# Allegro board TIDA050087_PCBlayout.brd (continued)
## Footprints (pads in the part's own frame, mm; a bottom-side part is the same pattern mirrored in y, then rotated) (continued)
MH_CIR173D106T_CUST
  round 4.394 hole 2.692: 1(0,0)
RC0603
  oval 0.889x1.143 smd: 1(-0.762,0) 2(0.762,0)
RC0805
  oval 0.889x1.524 smd: 1(-0.965,0) 2(0.965,0)
SON8_0P5_3X2_EP_A1
  rect 0.635x0.254 smd: 1(-1.412,0.75) 2(-1.412,0.25) 3(-1.412,-0.25) 4(-1.412,-0.75) 5(1.412,-0.75) 6(1.412,-0.25) 7(1.412,0.25) 8(1.412,0.75)
  rect 1.6x1.6 smd: 9(0,0)
SOT23-3L_1P9_2P9X1P3_A1
  rect 0.813x0.914 smd: 1(-0.95,-1) 2(0.95,-1) 3(0,1)
SOT23-5L_0P95_2P9X1P6_E_A1
  rect 0.61x1.092 smd: 1(-0.95,-1.3) 2(0,-1.3) 3(0.95,-1.3) 4(0.95,1.3) 5(-0.95,1.3)
SOT23-6L_0P95_2P9X1P6_K_A1
  rect 0.61x1.118 smd: 1(-0.95,-1.321) 2(0,-1.321) 3(0.95,-1.321) 4(0.95,1.321) 5(0,1.321) 6(-0.95,1.321)
SOT323-3L_1P3_2X1P25_A2
  rect 0.711x0.889 smd: 1(-0.648,-0.952) 2(0.648,-0.952) 3(0,0.952)
SOT563-6L_0P5_1P6X1P2_A_A1
  rect 0.305x0.66 smd: 1(-0.5,-0.74) 2(0,-0.74) 3(0.5,-0.74) 4(0.5,0.74) 5(0,0.74) 6(-0.5,0.74)
TP20_SMD
  round 0.381 smd: 1(0,0)
TP35_SMD
  round 0.889 smd: 1(0,0)
TP50_SMD
  round 1.27 smd: 1(0,0)
unnamed#2
  round 0.508 smd: (0,0)
UQFN16_0P65_4X4_EP_A1
  rect 0.787x0.356 smd: 1(-1.975,0.975) 2(-1.975,0.325) 3(-1.975,-0.325) 4(-1.975,-0.975) 9(1.975,-0.975) 10(1.975,-0.325) 11(1.975,0.325) 12(1.975,0.975)
  rect 0.356x0.787 smd: 5(-0.975,-1.975) 6(-0.325,-1.975) 7(0.325,-1.975) 8(0.975,-1.975) 13(0.975,1.975) 14(0.325,1.975) 15(-0.325,1.975) 16(-0.975,1.975)
  rect 2.692x2.692 smd: 17(0,0)
VQFN32_0P4_4X4_EP_A1
  rect 0.559x0.203 smd: 1(-1.925,1.4) 2(-1.925,1) 3(-1.925,0.6) 4(-1.925,0.2) 5(-1.925,-0.2) 6(-1.925,-0.6) 7(-1.925,-1) 8(-1.925,-1.4) 17(1.925,-1.4) 18(1.925,-1) 19(1.925,-0.6) 20(1.925,-0.2) 21(1.925,0.2) 22(1.925,0.6) 23(1.925,1) 24(1.925,1.4)
  rect 0.203x0.559 smd: 9(-1.4,-1.925) 10(-1,-1.925) 11(-0.6,-1.925) 12(-0.2,-1.925) 13(0.2,-1.925) 14(0.6,-1.925) 15(1,-1.925) 16(1.4,-1.925) 25(1.4,1.925) 26(1,1.925) 27(0.6,1.925) 28(0.2,1.925) 29(-0.2,1.925) 30(-0.6,1.925) 31(-1,1.925) 32(-1.4,1.925)
  rect 2.794x2.794 smd: 33(0,0)
WSON10_0P5_2X3_EP_B_A1
  rect 0.457x0.254 smd: 1(-0.975,1) 2(-0.975,0.5) 3(-0.975,0) 4(-0.975,-0.5) 5(-0.975,-1) 6(0.975,-1) 7(0.975,-0.5)
  rect 0.559x1.499 smd: 10(0.975,0.58)
  rect 1.092x2.692 smd: 11(0,0)
X2SON4_0P65_1X1_EP_A1
  custom 0.077x0.077 smd: 1(-0.43,0.325) 2(-0.43,-0.325) 3(0.43,-0.325) 4(0.43,0.325)
  rect 0.483x0.483 smd rot 45: 5(0,0)
XTAL2_2P5_3P2X1P5
  rect 1.092x1.905 smd: 1(-1.25,0) 2(1.25,0)
XTAL4_1P6_3P2X2P5_A_A1
  rect 1.397x1.194 smd: 1(-1.1,-0.8) 2(1.1,-0.8) 3(1.1,0.8) 4(-1.1,0.8)

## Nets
GND: BH801.1 BH802.1 BH803.1 BH804.1 C101.2 C102.2 C106.2 C107.2 C108.2 C109.2 C110.2 C111.2 C114.2 C116.2 C117.2 C118.2 C119.2 C124.2 C129.2 C130.2 C131.2 C132.2 C134.2 C135.2 C136.2 C137.2 C138.2 C139.2 C140.2 C141.2 C142.2 C143.2 C144.2 C145.2 C146.2 C147.2 C148.2 C149.2 C151.2 C152.2 C153.2 C154.2 C155.2 C156.2 C201.2 C202.2 C203.2 C204.2 C205.2 C206.2 C207.2 C208.2 C209.2 C210.2 C211.2 C212.2 C213.2 C214.2 C215.2 C216.2 C217.2 C218.2 C219.2 C220.2 C221.2 C222.2 C401.2 C402.2 C403.2 C404.2 C405.2 C501.2 C502.2 C503.2 C504.2 C505.2 C506.2 C507.2 C508.2 C509.2 C702.1 C704.1 C706.1 C707.2 C708.2 C709.2 C712.1 C713.2 C714.2 C715.1 C718.2 C720.2 C721.1 C722.1 C723.1 C724.1 C725.2 C726.2 C727.2 C729.2 C730.2 C731.2 C801.2 C802.2 C803.2 C804.2 C805.2 C806.2 C807.2 C808.2 C809.2 C901.2 C903.2 C904.2 C906.2 C909.2 C911.2 C912.2 C913.2 C914.2 C915.2 C916.2 C918.2 C922.2 C923.2 C925.2 C926.2 C928.2 C929.2 C930.2 C931.2 C934.2 C935.2 C937.2 C938.2 C942.2 C943.2 C944.2 C946.2 C947.2 C951.2 C952.2 C953.2 C954.2 C996.1 C1013.1 C1021.2 C1022.2 C1023.2 C1024.2 D601.1(K) J801.11 J801.12 J801.13 J801.14 J801.15 J801.16 J801.17 J801.18 J801.28 J801.30 J801.35 J801.36 J801.45 J801.46 J801.52 J801.55 J801.62 J801.65 J801.71 J801.72 J802.1 J802.2 J802.7 J802.8 J802.13 J802.14 J802.19 J802.20 J802.25 J802.26 J802.31 J802.32 J802.37 J802.38 J802.43 J802.44 J802.48 J802.49 J802.54 J802.55 J802.60 J802.65 J802.66 J802.70 J802.71 J802.76 J802.79 J803.9 J803.10 J803.19 J803.20 J803.29 J803.30 J803.39 J803.40 J803.49 J803.50 J803.57 J803.60 J803.67 J803.68 J803.75 J803.76 J803.81 J803.82 J803.83 J803.84 J803.85 J803.86 J803.87 J803.88 J901.2 J901.12 R201.2 R204.2 R207.1 R208.1 R302.1 R303.2 R305.2 R403.2 R415.2 R416.2 R417.2 R418.2 R609.2 R610.2 R611.2 R612.2 R614.2 R912.2 R913.2 R930.2 R933.2 R950.2 R955.2 R978.2 R979.2 R980.2 R981.2 R982.2 R992.2 R993.2 R1023.2 R1024.2 R1088.2 R1090.2 R1095.2 R1099.2 R1100.2 R1104.1 TP615.1 TP617.1 TP801.1 TP802.1 TP803.1 TP804.1 U101.A1 U101.A21 U101.AA1 U101.AA21 U101.C2 U101.C4 U101.C6 U101.C8 U101.C10 U101.C12 U101.C14 U101.C16(VSS9) U101.C18 U101.E3 U101.E19 U101.G3 U101.G19 U101.H8 U101.H10 U101.H12 U101.H14 U101.J3 U101.J5 U101.J8 U101.J14 U101.J19 U101.K11 U101.L1 U101.L3 U101.L5 U101.L8 U101.L14 U101.L19 U101.M11 U101.N3 U101.N5 U101.N8 U101.N14 U101.N19 U101.P8 U101.P10 U101.P12 U101.P14 U101.R3 U101.R19 U101.T1 U101.U3 U101.U19 U101.W4 U101.W6 U101.W10 U101.W12 U101.W14 U101.W16 U101.W18 U201.A3 U201.A10 U201.AB3 U201.AB5 U201.AB8 U201.AB10 U201.C1 U201.C5 U201.C8 U201.C12 U201.D2 U201.D4 U201.D9 U201.D11 U201.E1 U201.E5 U201.E8 U201.E12 U201.G1 U201.G3 U201.G5 U201.G8 U201.G10 U201.G12 U201.J1 U201.J3 U201.J10 U201.J12 U201.K2 U201.K4 U201.K9 U201.K11 U201.N2 U201.N4 U201.N9 U201.N11 U201.P1 U201.P3 U201.P10 U201.P12 U201.T1 U201.T3 U201.T5 U201.T8 U201.T10 U201.T12 U201.V1 U201.V5 U201.V8 U201.V12 U201.W2 U201.W4 U201.W9 U201.W11 U201.Y1 U201.Y5 U201.Y8(VSS_Y8) U201.Y12 U501.A6 U501.C4 U501.E7 U501.G5 U501.H10 U501.J5 U501.K8 U501.N2 U501.N5 U501.P4 U501.P6 U701.15 U701.33 U901.4 U902.3 U902.17 U903.6 U904.3 U904.17 U905.2 U906.6 U907.3 U907.17 U908.6 U909.13 U909.17 U910.6 U911.3 U911.17 U912.3 U912.17 U913.4 U913.5 U913.6 U913.7 U913.9 U914.2(VSS) U919.1 U920.2 U920.5 Y401.2 Y401.4(GND2)
PVIN_LDO2: C996.2 R1084.2 R1085.2 U701.20
PVIN_LDO34: C724.2 R1069.2 R1070.2 U701.22
VBUS1_DET_3V3: R301.1 U101.F12
VBUS2_DET_3V3: R304.1 U101.E14
VDD2_DDR: C136.1 C137.1 C138.1 C139.1 C140.1 C141.1 C156.1 R109.1 R939.1 R944.2 R958.1 TP930.1 U101.L7 U101.N6 U101.N7 U101.R6 U101.T6
VDD_1P8: C719.1 C720.1 L705.2 R727.1 R1041.1 R1044.1 R1087.1 TP707.1 TP959.1
VDD_1V8: C504.1 C505.1 C506.1 C507.1 C805.1 J801.19 J801.20 J801.21 J801.22 J801.23 J801.24 J801.25 J801.26 L102.1 Q902.1 Q903.1 R106.2 R202.1 R501.1 R502.1 R712.1 R713.1 R727.2 R1004.1 R1005.1 R1014.1 R1028.1 R1041.2 R1045.1 TP942.1 TP946.1 TP960.1 U501.C6 U501.M4 U501.N4 U501.P3 U501.P5
VDD_3P3: C714.1 C715.2 L704.2 R726.1 R1040.1 R1042.1 R1092.2 TP706.1 TP957.1
VDD_3V3: C501.1 C502.1 C503.1 C803.1 J803.91 J803.92 J803.93 J803.94 J803.95 J803.96 J803.97 J803.98 J803.99 J803.100 R105.1 R107.2 R605.1 R726.2 R987.1 R991.1 R1002.1 R1003.1 R1040.2 R1043.1 R1065.1 R1069.1 R1084.1 TP940.1 TP956.1 TP958.1 U501.E6 U501.F5 U501.J10 U501.K9
VDD_ANA_0P8: C130.1 C131.1 C132.1 C134.1 C135.1 R103.2 R999.2 R1000.1 TP937.1 U101.F10 U101.G8 U101.J15 U101.J16 U101.R14
VDD_ANA_0V8: C730.1 R103.1 R997.1 R999.1 TP712.1 TP936.1 U701.19
VDD_ANA_1P8: C142.1 C143.1 C144.1 C145.1 C146.1 C147.1 C148.1 C149.1 R104.2 R909.1 R1001.2 TP939.1 U101.E8 U101.F6 U101.F8 U101.F16 U101.G16 U101.L15 U101.R8
VDD_ANA_1V8: L102.2 R104.1 R111.2 R905.1 R1001.1 TP938.1
VDD_SNVS_0V8: C102.1 U101.G14
VDD_SOC: C106.1 C107.1 C108.1 C109.1 C110.1 C111.1 C114.1 C124.1 R102.2 R927.1 R932.2 R1020.1 TP927.1 U101.J9 U101.J10 U101.J11 U101.J12 U101.J13 U101.K9 U101.K10 U101.K12 U101.K13 U101.M9 U101.M10 U101.M12 U101.M13 U101.N9 U101.N10 U101.N11 U101.N12 U101.N13
VDD_SOC_0V85: C707.1 C708.1 C1024.1 L702.2 R102.1 R931.1 R1008.1 R1091.2 TP703.1 TP925.1 U906.3 U906.11
VDD_USB_3P3: C155.1 R105.2 R996.1 R1002.2 TP941.1 U101.G10
VDDQ_DDR: C151.1 C152.1 C153.1 C154.1 R110.1 R943.1 R947.1 R974.2 TP933.1 U101.G6 U101.J6 U101.J7 U101.L6
ADC_IN0: J802.72 TP413.1 U101.B19
ADC_IN1: J802.74 TP414.1 U101.A20
ADC_IN2: J802.78 TP415.1 U101.B20
ADC_IN3: J802.80 TP416.1 U101.B21
BB_VSYS_5V: C801.1 C802.1 C918.1 J801.1 J801.2 J801.3 J801.4 J801.5 J801.6 J801.7 J801.8 J801.9 J801.10 R802.2 R901.1 R911.1 TP901.1 TP919.1 U901.1 U901.9 U905.1 U905.3
CLKIN1: J802.67 R415.1 TP418.1 U101.B17
CLKIN2: J802.69 R416.1 TP419.1 U101.A18
CLKO01: J801.79 U101.AA2
CLKO02: J801.77 U101.Y3
CLKO03: J801.75 U101.U4
CLKO04: J801.73 U101.V4
CSI_CLK_N: J802.47 U101.D10
CSI_CLK_P: J802.45 U101.E10
CSI_D0_N: J802.41 U101.A11
CSI_D0_P: J802.39 U101.B11
CSI_D1_N: J802.35 U101.A10
CSI_D1_P: J802.33 U101.B10
DRAM_CA0_A: U101.H2 U201.H2
DRAM_CA1_A: U101.G1 U201.J2
DRAM_CA2_A: U101.F2 U201.H9
DRAM_CA3_A: U101.E1 U201.H10
DRAM_CA4_A: U101.E2 U201.H11
DRAM_CA5_A: U101.D1 U201.J11
DRAM_CK_C_A: R205.2 U101.G5 U201.J9
DRAM_CK_T_A: R205.1 U101.G4 U201.J8
DRAM_CKE0_A: R207.2 U101.H1 U201.J4
DRAM_CKE1_A: R208.2 U101.J4 U201.J5
DRAM_DATA0_A: TP206.1 U101.N1 U201.F4
DRAM_DATA1_A: TP209.1 U101.N2 U201.E4
DRAM_DATA2_A: U101.M1 U201.C4
DRAM_DATA3_A: TP205.1 U101.M2 U201.B4
DRAM_DATA4_A: TP207.1 U101.K1 U201.B2
DRAM_DATA5_A: TP208.1 U101.K2 U201.C2
DRAM_DATA6_A: U101.J1 U201.E2
DRAM_DATA7_A: TP204.1 U101.J2 U201.F2
DRAM_DATA8_A: U101.V1 U201.E11
DRAM_DATA9_A: TP216.1 U101.V2 U201.F11
DRAM_DATA10_A: TP215.1 U101.U2 U201.C11
DRAM_DATA11_A: TP214.1 U101.U1 U201.B11
DRAM_DATA12_A: U101.R1 U201.C9
DRAM_DATA13_A: TP213.1 U101.R2 U201.B9
DRAM_DATA14_A: TP211.1 U101.P2 U201.E9
DRAM_DATA15_A: TP212.1 U101.P1 U201.F9
DRAM_DMI0_A: TP201.1 U101.L2 U201.C3
DRAM_DMI1_A: TP210.1 U101.T2 U201.C10
DRAM_NCS0_A: U101.F1 U201.H4
DRAM_NCS1_A: U101.G2 U201.H3
DRAM_NRESET: R201.1 U101.D2 U201.T11
DRAM_SDQS0_C_A: U101.L4 U201.E3
DRAM_SDQS0_T_A: U101.N4 U201.D3
DRAM_SDQS1_C_A: U101.R5 U201.E10
DRAM_SDQS1_T_A: U101.R4 U201.D10
DRAM_ZN: R204.1 U101.E4
DRAM_ZQ0: R209.2 U201.A5
DSI_CLK_N: J802.3 U101.D6
DSI_CLK_P: J802.5 U101.E6
DSI_D0_N: J802.9 U101.A6
DSI_D0_P: J802.11 U101.B6
DSI_D1_N: J802.15 U101.A7
DSI_D1_P: J802.17 U101.B7
DSI_D2_N: J802.21 U101.A8
DSI_D2_P: J802.23 U101.B8
DSI_D3_N: J802.27 U101.A9
DSI_D3_P: J802.29 U101.B9
EMMC_VDDIM: C508.1 C509.1 U501.C2
ENET1_MDC: J801.37 U101.AA11
ENET1_MDIO: J801.39 U101.AA10
ENET1_RD0: J801.49 U101.AA8
ENET1_RD1: J801.47 U101.Y9
ENET1_RD2: J801.43 U101.AA9
ENET1_RD3: J801.41 U101.Y10
ENET1_RX_CTL: J801.51 U101.Y8
ENET1_RXC: J801.53 U101.AA7
ENET1_TD0: J801.44 U101.W11
ENET1_TD1: J801.42 U101.T12
ENET1_TD2: J801.40 U101.U12
ENET1_TD3: J801.38 U101.V12
ENET1_TX_CTL: J801.48 U101.V10
ENET1_TXC: J801.50 U101.U10
ENET2_MDC: J801.54 U101.Y7
ENET2_MDIO: J801.56 U101.AA6
ENET2_RD0: J801.63 U101.AA4
ENET2_RD1: J801.61 U101.Y5
ENET2_RD2: J801.59 U101.AA5
ENET2_RD3: J801.57 U101.Y6
ENET2_RX_CTL: J801.67 U101.Y4
ENET2_RXC: J801.69 U101.AA3
ENET2_TD0: J801.66 U101.T8
ENET2_TD1: J801.64 U101.U8
ENET2_TD2: J801.60 U101.V8
ENET2_TD3: J801.58 U101.T10
ENET2_TX_CTL: J801.68 U101.V6
ENET2_TXC: J801.70 U101.U6
FSC_CTRL_H1: R969.2 TP909.1 U901.2
FSC_CTRL_H2: R970.2 TP910.1 U903.5
FSC_CTRL_H3: R972.2 TP911.1 U906.5
FSC_CTRL_H4: R1034.2 TP917.1 U908.5
FSC_CTRL_H5: R1035.2 TP918.1 U910.5
FSC_CTRL_L1: R960.2 TP961.1
FSC_CTRL_L2: R962.2 TP962.1
FSC_CTRL_L3: R963.2 TP963.1
FSC_CTRL_L4: R964.2 TP964.1
FSC_CTRL_L5: R966.2 TP965.1
FT_EECLK: J901.7 R1016.2
FT_EECS: J901.10 R1018.2
FT_EEDATA: J901.9 R1015.2
FT_IO_NINT: J901.4 R961.1 TP906.1
FT_IO_NRST: D903.1(K) J901.6 TP907.1
FT_IOEXP1_SCL: R968.2 U909.15
FT_IOEXP1_SDA: R965.2 U909.14
FT_SCL: J901.3 R906.2 R926.2 R946.2 R968.1 R988.2 R1019.2 R1033.1 TP904.1
FT_SDA: J901.5 R910.2 R928.2 R948.2 R965.1 R990.2 R1021.2 R1032.1 TP905.1
GPIO_IO00: J803.22 U101.J21
GPIO_IO01: J803.24 U101.J20
GPIO_IO02: J803.28 U101.K20
GPIO_IO03: J803.26 U101.K21
GPIO_IO04: J803.23 U101.L17
GPIO_IO05: J803.21 U101.L18
GPIO_IO06: J803.27 U101.L20
GPIO_IO07: J803.25 U101.L21
GPIO_IO08: J803.33 U101.M20
GPIO_IO09: J803.31 U101.M21
GPIO_IO10: J803.34 U101.N17
GPIO_IO11: J803.32 U101.N18
GPIO_IO12: J803.37 U101.N20
GPIO_IO13: J803.35 U101.N21
GPIO_IO14: J803.42 U101.P20
GPIO_IO15: J803.41 U101.P21
GPIO_IO16: J803.43 U101.R21
GPIO_IO17: J803.44 U101.R20
GPIO_IO18: J803.36 U101.R18
GPIO_IO19: J803.38 U101.R17
GPIO_IO20: J803.48 U101.T20
GPIO_IO21: J803.46 U101.T21
GPIO_IO22: J803.45 U101.U18
GPIO_IO23: J803.52 U101.U20
GPIO_IO24: J803.47 U101.U21
GPIO_IO25: J803.51 U101.V21
GPIO_IO26: J803.53 U101.V20
GPIO_IO27: J803.54 U101.W21
GPIO_IO28: J803.56 U101.W20
GPIO_IO29: J803.58 U101.Y21
I2C1_SCL: J803.4 R307.2 R717.2 U101.C20
I2C1_SDA: J803.2 R306.2 R719.2 U101.C21
I2C2_SCL: J803.8 R309.2 R714.2 U101.D20
I2C2_SDA: J803.6 R308.2 R715.2 U101.D21
JTAG_TCK: J801.76 R403.1 TP404.1 U101.Y1
JTAG_TDI: J801.80 TP402.1 U101.W1
JTAG_TDO: J801.74 TP405.1 U101.Y2
JTAG_TMS: J801.78 TP403.1 U101.W2
LPD4/X_VDD1: C201.1 C202.1 C203.1 C204.1 C205.1 C209.1 R202.2 R1006.1 R1014.2 TP947.1 U201.F1 U201.F12 U201.G4 U201.G9 U201.T4 U201.T9 U201.U1 U201.U12
LPD4/X_VDD2: C206.1 C207.1 C208.1 C210.1 C211.1 C212.1 C213.1 C214.1 R203.2 R210.1 R1017.2 R1026.1 TP951.1 U201.A4 U201.A9 U201.AB4 U201.AB9 U201.F5 U201.F8 U201.H1 U201.H5 U201.H8 U201.H12 U201.K1 U201.K3 U201.K10 U201.K12 U201.N1 U201.N3 U201.N10 U201.N12 U201.R1 U201.R5 U201.R8 U201.R12 U201.U5 U201.U8
LPD4/X_VDD2_1V1: C722.2 C723.2 L706.2 R109.2 R203.1 R702.1 R942.1 R949.1 R1017.1 R1022.1 R1093.2 TP708.1 TP928.1 TP950.1 U908.3 U908.11
LPD4/X_VDDQ: C215.1 C216.1 C217.1 C218.1 C219.1 C220.1 C221.1 C222.1 R206.2 R209.1 R211.1 R923.1 R1007.2 TP949.1 U201.AA3 U201.AA5 U201.AA8 U201.AA10 U201.B3 U201.B5 U201.B8 U201.B10 U201.D1 U201.D5 U201.D8 U201.D12 U201.F3 U201.F10 U201.U3 U201.U10 U201.W1 U201.W5 U201.W8 U201.W12
LPD4/X_VDDQ_0V6: R110.2 R206.1 R702.2 R921.1 R941.1 R973.1 R1007.1 TP931.1 TP948.1 U910.3 U910.11
LVDS_CLK_N: J802.18 U101.A3
LVDS_CLK_P: J802.16 U101.B3
LVDS_TX0_N: J802.30 U101.A5
LVDS_TX0_P: J802.28 U101.B5
LVDS_TX1_N: J802.24 U101.A4
LVDS_TX1_P: J802.22 U101.B4
LVDS_TX2_N: J802.12 U101.A2
LVDS_TX2_P: J802.10 U101.B2
LVDS_TX3_N: J802.6 U101.B1
LVDS_TX3_P: J802.4 U101.C1
M1_SCL: R906.1 U902.4
M1_SDA: R910.1 U902.5
M2_SCL: R926.1 U904.4
M2_SDA: R928.1 U904.5
M3_SCL: R946.1 U907.4
M3_SDA: R948.1 U907.5
M4_SCL: R988.1 U911.4
M5_SCL: R1019.1 U912.4
M5_SDA: R1021.1 U912.5
MX_POR_B: C405.1 R404.2 R406.2 TP408.1 U101.A16
NVCC_1P8: C116.1 C117.1 R106.1 R1004.2 R1029.1 TP943.1 U101.R10 U101.R12 U101.W8
NVCC_3P3: R107.1 R112.2 R113.2 R989.1 R1003.2 TP952.1
NVCC_AON: C119.1 C804.1 J803.90 R112.1 R306.1 R307.1 R308.1 R309.1 R601.1 R602.1 R603.1 R604.1 TP608.1 U101.L16
NVCC_BBSM_1P8: C101.1 R101.2 R903.1 R918.1 R920.2 TP924.1 U101.G12
NVCC_BBSM_1V8: C727.1 C809.1 J802.53 Q901.1 R101.1 R401.1 R404.1 R405.1 R703.1 R902.1 R919.1 R971.1 R1064.1 R1096.1 R1097.1 R1102.1 TP709.1 TP922.1 U903.3 U903.11 U920.1(OUT)
NVCC_BBSM_PULL UP: R703.2 R706.1 U701.28
NVCC_GPIO: C118.1 C806.1 J803.89 R113.1 U101.N15 U101.N16
NVCC_SD: C731.1 R108.2 R929.1 R998.1 TP713.1 TP934.1 U701.7
NVCC_SD2: C129.1 C808.1 J803.55 R108.1 R310.1 R311.1 R312.1 R935.1 R998.2 TP935.1 U101.R16
ODT_CA_A: R210.2 U201.G2
ONOFF: J802.75 R405.2 TP401.1 U101.A19
PDM_CLK: J803.11 U101.G17
PDM_DATA0: J803.13 U101.J17
PDM_DATA1: J803.15 U101.G18
PMIC_32K_OUT: J801.34 R411.1
PMIC_NINT: J801.32 U701.11
PMIC_ON_REQ: J802.63 R401.2 R418.1 R707.1 TP407.1 U101.A17
PMIC_SCLH: J801.31 R724.2
PMIC_SCLL: J801.27 Q903.2(SOURCE) R712.2
PMIC_SDAH: J801.33 R725.2
PMIC_SDAL: J801.29 Q902.2(SOURCE) R713.2
PMIC_STBY_REQ: J802.73 R417.1 TP409.1 U101.B18
POR_B: J802.57 Q901.2(SOURCE) R406.1 R971.2 R1059.2 R1098.2
S1_CPU_VDD2_DDR: R937.1 R942.2 R944.1 TP929.1 U908.10(VOUT)
S1_CPU_VDDQ_DDR: R945.1 R973.2 R974.1 TP932.1 U910.10(VOUT)
S1_NVCC_BBSM_1V8: R917.1 R919.2 R920.1 TP923.1 U903.10(VOUT)
S1_VDD_SOC_0V85: R924.1 R931.2 R932.1 TP926.1 U906.10(VOUT)
S1_VSYS_5V: R901.2 R904.1 R908.1 R983.1 TP920.1 U901.7(VOUT)
SAI1_RXD0: J803.18 U101.H20
SAI1_TXC: J803.14 U101.G20
SAI1_TXD0: J803.16 R604.2 R612.1 TP604.1 U101.H21
SAI1_TXFS: J803.12 R603.2 R611.1 TP603.1 U101.G21
SD1_CLK: TP503.1 U101.Y11 U501.M6
SD1_CMD: R502.2 TP502.1 U101.AA12 U501.M5
SD1_DATA0: R501.2 TP501.1 U101.AA14 U501.A3
SD1_DATA1: U101.AA15 U501.A4
SD1_DATA2: U101.AA16 U501.A5
SD1_DATA3: U101.AA13 U501.B2
SD1_DATA4: U101.Y13 U501.B3
SD1_DATA5: U101.Y14 U501.B4
SD1_DATA6: U101.Y15 U501.B5
SD1_DATA7: U101.Y16 U501.B6
SD1_STROBE: TP505.1 U101.Y12 U501.H5
SD2_CLK: J803.65 U101.AA19
SD2_CMD: J803.63 R311.2 U101.Y19
SD2_DATA0: J803.69 R310.2 U101.Y18
SD2_DATA1: J803.71 U101.AA18
SD2_DATA2: J803.59 U101.Y20
SD2_DATA3: J803.61 U101.AA20
SD2_NCD: J803.73 U101.Y17
SD2_RESET_B: R312.2 TP972.1 U101.AA17
SD2_VSEL: R1083.2 R1100.1 U101.V18
SD3_CLK: J803.62 U101.V16
SD3_CMD: J803.64 U101.U16
SD3_DATA0: J803.66 U101.T16
SD3_DATA1: J803.70 U101.V14
SD3_DATA2: J803.72 U101.U14
SD3_DATA3: J803.74 U101.T14
SYS_NRST: J802.77 R706.2 TP915.1
TAMPER0: J802.61 TP410.1 U101.B16
TAMPER1: J802.59 TP411.1 U101.F14
TEMP_NINT: R1009.2 TP908.1 U913.3
TPS65219_GPIO1: R1094.1 R1095.1 U919.4
UART1_RXD: J803.3 TP612.1 U101.E20
UART1_TXD: J803.1 R601.2 R609.1 TP610.1 U101.E21
UART2_RXD: J803.7 TP616.1 U101.F20
UART2_TXD: J803.5 R602.2 R610.1 TP614.1 U101.F21
USB1_DN: J802.50 TP611.1 U101.A14
USB1_DP: J802.52 TP613.1 U101.B14
USB1_ID: J802.56 U101.C11
USB1_RXN: J802.34 U101.A12
USB1_RXP: J802.36 U101.B12
USB1_TXN: J802.40 U101.A13
USB1_TXP: J802.42 U101.B13
USB1_VBUS: R613.1 TP609.1
USB1_VBUS_3V3: J802.46 R301.2 R613.2 R614.1
USB2_DN: J802.62 U101.A15
USB2_DP: J802.64 U101.B15
USB2_ID: J802.68 U101.E12
USB2_VBUS_3V3: J802.58 R304.2
VLDO3_1V8: C729.1 R111.1 TP711.1 U701.21
VLS_3V3: C901.1 C906.1 C909.1 C912.1 C922.1 C923.1 C930.1 C931.1 C935.1 C938.1 D901.1(K) D902.1(K) R907.2 R922.2 R938.2 R951.2 R985.2 TP903.1 U901.3 U903.4 U906.4 U908.4 U910.4
VMEAS_3V3: C903.1 C904.1 C911.1 C913.1 C915.1 C916.1 C925.1 C926.1 C928.1 C929.1 C934.1 C937.1 C942.1 C943.1 C944.1 C946.1 C947.1 D902.2 J901.1 J901.11 R914.2 R915.2 R934.2 R936.2 R952.1 R953.1 R956.2 R959.2 R975.1 R976.1 R977.1 R994.2 R995.2 R1009.1 R1011.1 R1012.1 R1013.1 R1025.2 R1027.2 R1036.1 R1037.1 TP902.1 U902.2 U902.15(VDD_I/O) U904.2 U904.15(VDD_I/O) U907.2 U907.15(VDD_I/O) U909.12(VDD) U911.2 U911.15(VDD_I/O) U912.2 U912.15(VDD_I/O) U913.8(VCC) U914.6
VSD2_3V3: C807.1 J803.77 J803.78 J803.79 J803.80 R801.2 R967.1 R1031.2 TP945.1
VSD_3V3: C725.1 R801.1 R957.1 R1031.1 TP944.1 U701.23
VSYS_5V: C702.2 C704.2 C709.1 C712.2 C713.1 C718.1 C721.2 C726.1 C1021.1 C1022.1 C1023.1 R802.1 R904.2 R916.1 R984.1 R1066.1 R1070.1 R1085.1 R1089.1 TP607.1 TP921.1 U701.4 U701.5 U701.13(VSYS) U701.26 U701.30 U919.3(VIN) U920.4
WDOG_B: J803.17 U101.J18
XTALI_24M: C403.1 R414.1 TP417.1 U101.D18 Y401.1
XTALI_32K: R411.2 R412.1 TP412.1 U101.E16
XTALO_24M: C404.1 R414.2 U101.E18 Y401.3
XTALO_32K: C402.1 QZ401.1 R413.2 U101.D16
N113524078: C401.1 QZ401.2 R412.2 R413.1
N113540349: D903.2 D904.2 R952.2 U909.11
N113540351: R953.2 R961.2 U909.16
N113540485: R960.1 R982.1 U909.5
N113540576: R962.1 R981.1 U909.4
N113540605: C914.1 D901.2 R1103.2 U905.5(OUT)
N113540646: R963.1 R980.1 U909.3
N113540680: R964.1 R979.1 U909.2
N113540755: R966.1 R978.1 U909.1
N113540996: D904.1(K) Q901.3
N113787187: R915.1 U902.16
N113787601: R912.1 U902.6
N113787940: R913.1 R914.1 U902.1
N113791010: C902.1 R902.2 R1044.2 U902.11
N113791044: C902.2 R903.2 R1045.2 U902.12
N113791152: C907.1 R911.2 R1042.2 U902.8
N113791186: C907.2 R916.2 R1043.2 U902.7
N113791216: C908.1 R917.2 U902.10
N113791250: C908.2 R918.2 U902.9
N113798682: C910.1 R921.2 U904.11
N113798752: C910.2 R923.2 U904.12
N113798791: C917.1 R924.2 U904.13
N113798839: C917.2 R927.2 U904.14
N113798887: C920.1 R929.2 U904.8
N113798893: R930.1 U904.6
N113798925: R933.1 R934.1 U904.1
N113798968: C920.2 R935.2 U904.7
N113799011: C921.1 R937.2 U904.10
N113799045: C921.2 R939.2 U904.9
N113816310: C924.1 R941.2 U907.11
N113816380: C924.2 R943.2 U907.12
N113816419: C927.1 R945.2 U907.13
N113816455: C927.2 R947.2 U907.14
N113816503: C932.1 R949.2 U907.8
N113816509: R950.1 U907.6
N113816541: R955.1 R956.1 U907.1
N113816573: C932.2 R958.2 U907.7
N113819379: C936.1 R983.2 U911.11
N113819449: C936.2 R984.2 U911.12
N113819488: C939.1 R987.2 U911.13
N113819524: C939.2 R989.2 U911.14
N113819572: C940.1 R991.2 U911.8
N113819642: C940.2 R996.2 U911.7
N113819644: R993.1 R994.1 U911.1
N113819688: R995.1 U911.16
N113819696: C941.1 R997.2 U911.10
N113819730: C941.2 R1000.2 U911.9
N113821648: C945.1 R1005.2 U912.11
N113821718: C945.2 R1006.2 U912.12
N113821847: R1023.1 U912.6
N113821913: R1024.1 R1025.1 U912.1
N113821965: C950.1 R1028.2 U912.10
N113821999: C950.2 R1029.2 U912.9
N114152142: R302.2 U101.D8
N114616846: D601.2 R605.2
N114789657: R1012.2 R1016.1 TP954.1 U914.4
N114789678: R1013.2 R1018.1 TP955.1 U914.5
N114814991: R305.1 U101.D14
N114815134: R303.1 U101.D12
N115328449: C933.1 R957.2 U912.8
N115328489: C933.2 R967.2 U912.7
N115328624: C949.1 R1022.2 U907.10
N115328664: C949.2 R1026.2 U907.9
N115344996: C948.1 R1008.2 U902.13
N115345040: C948.2 R1020.2 U902.14
N115345198: C905.1 R905.2 U912.13
N115345238: C905.2 R909.2 U912.14
N115885549: R1010.1 R1011.2 U914.1
N115885630: R1010.2 R1015.1 TP953.1 U914.3
N115909883: R969.1 R977.2 U909.6
N115909890: R970.1 R976.2 U909.7
N115909893: R972.1 R975.2 U909.8
N115909896: R1034.1 R1037.2 U909.9
N115909899: R1035.1 R1036.2 U909.10
N115939435: C951.1 U903.1
N115957390: R922.1 U903.7
N115991020: C952.1 U906.1
N115994234: R938.1 U906.7
N115999748: C953.1 U908.1
N116003893: R951.1 U908.7
N116014384: C954.1 U910.1
N116018297: R985.1 U910.7
N116041401: R908.2 U901.5
N116046959: R907.1 U901.6
N116083878: R936.1 U904.16
N116107496: R959.1 U907.16
N116113800: R990.1 U911.5
N116121400: R992.1 U911.6
N116137130: R1027.1 U912.16
N116434057: C706.2 U701.14
N116434617: R707.2 U701.25
N116434822: L702.1 U701.2 U701.3
N116434898: L704.1 U701.29
N116434901: L706.1 U701.27
N116471687: R1059.1 U701.18
N116471690: R1083.1 U701.12
N116476004: C1013.2 R1065.2 R1066.2 U701.6
N116660464: R714.1 U701.10
N116660470: R715.1 U701.9
N116675602: TP202.1 U101.D4
N116676339: TP504.1 U501.K5
N116698763: R211.2 U201.A8
N116700633: J802.51 TP805.1
N116701055: R1033.2 U913.2
N116701070: R1032.2 U913.1
N116772045: L705.1 U919.2
N116772074: C719.2 R1087.2 R1088.1 U919.5
N116772436: R1089.2 R1090.1 U920.3
N116861023: Q903.3 R717.1 R724.1
N116861029: Q902.3 R719.1 R725.1
N116892698: R1097.2 TP969.1 U701.16
N116924893: R1091.1 U701.1
N116924896: R1092.1 U701.32
N116924899: R1093.1 U701.24
N116925021: R1099.1 R1102.2 U701.31
N116939248: R1064.2 R1094.2 U701.8
N116980775: R1096.2 TP970.1 U701.17
N116981199: R1098.1 U919.6
N117032871: R1103.1 R1104.2 U905.4

Pads without a net: J801 M1 M2 M3 M4; J802 M1 M2 M3 M4; J803 S1 S2 S3 S4; J901 8 M1 M2 M3 M4; U201 A1 A2 A11 A12 AA1 AA2 AA4 AA9 AA11 AA12 AB1 AB2 AB11 AB12 B1 B12 G11 K5 K8 N5 N8 P2 P4 P5 P8 P9 P11 R2 R3 R4 R9 R10 R11 T2 U2 U4 U9 U11 V2 V3 V4 V9 V10 V11 W3 W10 Y2 Y3 Y4 Y9 Y10 Y11; U501 A1 A2 A7 A8 A9 A10 A11 A12 A13 A14 B1 B7 B8 B9 B10 B11 B12 B13 B14 C1 C3 C5 C7 C8 C9 C10 C11 C12 C13 C14 D1 D2 D3 D4 D12 D13 D14 E1 E2 E3 E5 E8 E9 E10 E12 E13 E14 F1 F2 F3 F10 F12 F13 F14 G1 G2 G3 G10 G12 G13 G14 H1 H2 H3 H12 H13 H14 J1 J2 J3 J12 J13 J14 K1 K2 K3 K6 K7 K10 K12 K13 K14 L1 L2 L3 L12 L13 L14 M1 M2 M3 M7 M8 M9 M10 M11 M12 M13 M14 N1 N3 N6 N7 N8 N9 N10 N11 N12 N13 N14 P1 P2 P7 P8 P9 P10 P11 P12 P13 P14; U903 2; U906 2; U908 2; U910 2

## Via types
v1: diameter 0.406, hole 0.203, TOP to BOTTOM, 1165 vias
v2: diameter 1.422, hole 1.016, TOP to BOTTOM, 4 vias
v3: diameter 0.508, hole 0.254, TOP to BOTTOM, 51 vias

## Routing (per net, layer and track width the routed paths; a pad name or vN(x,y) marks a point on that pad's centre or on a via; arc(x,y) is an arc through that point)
GND: length 286.4
  TOP w0.076: 54.76,22.24 U501.N2 54.76,21.75 54.41,21.75 54.08,22.08 v1(54.08,22.13) 54.19,22.24 54.76,22.24
  TOP w0.203: U101.H10 51.68,40.2 v1(51.67,40.21) ; v1(56.01,19.03) 56.48,19.03 U501.K8 ; U101.H14 54.62,40.2 v1(54.69,40.13) ; U701.15 26.57,19.8 v1(26.17,20.2) ; v1(57.58,18.43) 57.58,18.07 U501.H10 ; v1(62.2,46.9) Y401.2 63.26,46.09 63.47,45.88 65.75,45.88 66.07,46.2 C404.2 ; v1(62.2,46.9) 62.2,45.57 v1(61.84,45.2) 61.84,44.73 60.43,43.32 59.06,43.32 v1(58.86,43.11) ; v1(62.2,46.9) 61.88,46.9 v1(61.55,47.22) 61.2,47.58 61.2,48.99 v1(61.88,49.68) 62.25,50.05 64.14,50.05 64.86,49.32 Y401.4 ; v1(23.2,53.06) 22.78,53.06 22.63,52.91 U909.13 ; C401.2 63.79,54.96 63.55,55.2 62.37,55.2 62.08,54.92 C402.2 ; v1(66.15,41.84) 66.97,42.66 TP617.1 ; U201.G8 37.92,36.43 v1(37.92,36.68) ; U101.W12 53.29,34.63 v1(53.75,34.63) 54.15,34.63 U101.W14 54.66,34.7 54.69,34.66 v1(54.71,34.66) 54.74,34.7 U101.W16 55.67,34.7 55.67,34.69 v1(55.83,34.69) 55.88,34.64 56.17,34.64 U101.W18 ; v1(59.57,20.56) 59.59,20.58 59.6,20.58 60.01,20.99 U501.C4 ; v1(64.86,51.59) 65.11,51.84 65.11,53.98 v1(64.44,54.65) ; TP802.1 38.82,58.89 v1(38.71,58.79) ; U501.J5 56.87,20.63 v1(56.87,21.01) ; v1(37.92,38.22) 37.92,38.46 U201.G5 ; v1(56.45,56.8) 56.45,56.68 R415.2 ; U901.4 v1(46.48,6.68) ; v1(61.54,19.84) 61.16,19.84 U501.A6 ; v1(54.47,56.57) 54.59,56.57 TP615.1 ; U101.L1 v1(47.27,38.7) ; R403.2 51.14,8.29 51,8.15 v1(51,7.62) ; U101.W10 51.82,34.7 51.82,34.69 v1(51.75,34.63) ; U101.N8 51.22,38.12 v1(51.28,38.18) ; v1(66.9,46.2) 67.16,46.46 v1(67.16,47.28) v1(67.16,48.58) 67.63,49.05 67.63,49.58 67.41,49.81 v1(66.93,49.81) ; U101.J8 U101.H8 v1(50.77,40.2) ; U501.P4 v1(54.13,20.99) ; v1(20.28,29.59) 20.27,29.59 20.22,29.64 U908.6 ; C153.2 32.29,31.56 v1(32.06,31.79) ; v1(37.9,42.28) 37.9,42.06 U201.G1 ; v1(57.97,20.03) 57.97,20.45 U501.G5 ; R614.2 55.09,59.46 v1(55.14,59.4) ; v1(54.1,19.93) 54.17,19.99 U501.P6 U501.N5 ; v1(60.92,51.67) 60.83,51.76 60.83,54.3 61.17,54.63 v1(61.46,54.63) ; C403.2 66.23,49.95 v1(65.72,49.95) ; v1(50.81,37.26) 51.16,37.26 U101.P8 ; U101.N14 v1(54.67,37.25) ; U101.P10 v1(51.72,37.2) ; U101.U19 v1(56.72,36.19) U101.R19 v1(56.72,37.2) U101.N19 v1(56.72,38.22) U101.L19 v1(56.72,39.2) U101.J19 56.72,40.16 v1(56.79,40.23) 56.72,40.3 U101.G19 56.72,41.07 v1(56.78,41.13) 56.78,41.63 U101.E19 ; U101.K11 52.72,38.6 v1(52.72,38.6) 52.72,38.59 U101.M11 ; U101.H12 53.68,40.2 53.7,40.17 v1(53.72,40.17) ; U101.T1 v1(47.28,36.2) ; v1(58.55,19.44) 58.64,19.53 58.98,19.53 U501.E7
  TOP w0.254: v1(33.23,32.65) 33.56,32.97 U201.P12 ; U201.E8 v1(39.41,36.68) ; v1(29.33,32.65) 29.66,32.97 U201.Y12 ; v1(33.88,34.25) 34.21,33.92 U201.N11 ; R950.2 18.11,35.56 v1(18.56,35.11) ; v1(49.76,40.2) 49.72,40.16 U101.J5 49.72,39.23 v1(49.76,39.2) 49.72,39.16 U101.L5 49.72,38.23 v1(49.76,38.2) 49.72,38.16 U101.N5 49.72,37.23 49.73,37.23 v1(49.73,37.15) ; U201.D2 39.7,40.68 v1(39.7,40.66) ; U101.A1 v1(47.41,44.01) ; v1(31.93,35.85) 32.26,36.17 U201.T8 ; v1(39.41,38.06) 39.41,38.06 U201.E5 ; U201.J12 36.48,32.71 v1(36.48,32.68) ; U201.W9 30.31,35.37 v1(29.98,35.05) ; U201.P3 33.56,40.32 v1(33.23,40.65) ; U101.AA1 v1(47.41,33.38) ; U201.N4 34.21,39.52 v1(33.88,39.85) ; U201.P1 33.56,41.92 v1(33.23,42.25) ; U201.V1 30.96,41.92 v1(30.63,42.25) ; v1(37.81,32.72) 37.81,32.75 U201.G12 ; v1(30.63,39.05) 30.96,38.72 U201.V5 ; U201.AB10 28.36,34.57 v1(28.03,34.25) ; U201.G10 37.75,34.29 v1(37.75,34.26) ; v1(33.23,34.25) 33.56,34.57 U201.P10 ; v1(35.79,33.55) 35.87,33.55 U201.K11 ; v1(56.72,42.7) U101.C18 55.73,42.7 v1(55.71,42.71) 55.71,42.7 U101.C16 54.76,42.7 v1(54.75,42.71) 54.73,42.7 U101.C14 54.17,42.75 53.8,42.75 v1(53.78,42.77) 53.72,42.71 53.72,42.7 U101.C12 ; v1(30.63,32.65) 30.96,32.97 U201.V12 ; U201.A10 42.66,34.65 v1(42.68,34.62) ; v1(40.98,36.58) 40.98,36.52 U201.C8 ; U201.W2 30.31,41.12 v1(29.98,41.45) ; v1(31.93,34.25) 32.26,34.57 U201.T10 ; v1(40.97,38.3) 40.97,38.38 U201.C5 ; U201.AB5 28.36,38.72 v1(28.03,39.05) ; U201.G3 38.42,39.94 v1(38.42,39.9) ; U201.V8 30.96,36.17 v1(30.63,35.85) ; v1(31.93,32.65) 32.26,32.97 U201.T12 ; v1(58.32,33.48) 57.94,33.48 U101.AA21 ; v1(33.88,35.85) 34.21,35.52 U201.N9 ; U201.AB8 28.36,36.17 v1(28.03,35.85) ; U201.K4 v1(35.81,39.1) ; C954.2 37.08,25.92 37.44,25.92 v1(37.51,25.98) ; v1(40.35,32.66) 40.35,32.69 U201.C12 ; v1(31.93,42.25) 32.26,41.92 U201.T1 ; U201.D9 40.36,35.75 v1(40.36,35.78) ; U201.E12 v1(39.41,32.54) ; v1(29.33,39.05) 29.66,38.72 U201.Y5 ; U201.K9 36.48,35.12 v1(36.48,35.09) ; U201.T3 32.26,40.32 v1(31.93,40.65) ; C808.2 65.83,31.82 v1(65.77,31.88) ; U201.T5 32.26,38.72 v1(31.93,39.05) ; U101.A21 v1(58.06,44.03) ; v1(40.37,39.11) 40.37,39.14 U201.D4 ; U201.D11 39.77,34.14 v1(39.77,34.21) ; v1(29.98,33.45) 30.31,33.77 U201.W11 ; v1(42.78,40.25) 42.78,40.25 U201.A3 ; v1(39.5,42.38) 39.41,42.29 U201.E1 ; v1(29.33,35.85) 29.66,36.17 U201.Y8 ; TP803.1 11.31,21.27 v1(10.42,20.38) ; U906.6 v1(45.43,19.79) ; v1(13.97,14.41) U903.6 ; R1023.2 5.47,9.05 ; v1(29.98,39.85) 30.31,39.52 U201.W4 ; U201.J1 36.55,42.1 v1(36.55,42.21) ; U201.C1 40.39,42.16 v1(40.39,42.2) ; v1(29.33,42.25) 29.66,41.92 U201.Y1 ; U201.K2 v1(35.83,41.38) ; C806.2 v1(65.27,27) ; v1(36.5,34.31) 36.5,34.34 U201.J10 ; U910.6 v1(39.02,29.05) ; v1(33.88,41.45) 34.21,41.12 U201.N2 ; R930.2 5.14,48.73 ; U201.J3 36.47,40.59 v1(36.47,40.62) ; v1(28.03,40.65) 28.36,40.32 U201.AB3
  TOP w0.305: v1(15.4,49.85) R980.2 R979.2 ; v1(3.25,52.98) 3.43,53.16 U904.3 ; R992.2 5.52,22.5 v1(5.68,22.34) ; C901.2 45.78,5.09 C906.2 44.51,5.09 44.1,4.68 v1(44.1,3.94) ; v1(5.38,46.23) C903.2 ; C931.2 17.5,24.56 C930.2 v1(16.79,24.56) ; C938.2 v1(35.28,23.96) ; C934.2 6,32.71 v1(6,33.18) ; R913.2 1.87,41.82 1.87,41.18 1.85,41.03 1.82,41 C904.2 v1(1.82,40.2) ; TP617.1 67.1,43.1 67.56,43.56 R611.2 ; R912.2 5.2,35.28 v1(5.23,35.24) ; U912.3 v1(3.74,13.73) ; C951.2 v1(15.61,17.55) ; v1(61.46,54.63) C402.2 ; v1(33.64,49.18) 33.44,49.38 U914.2 ; U911.3 v1(3.67,27.18) ; v1(1.96,27.21) 1.96,27.53 C937.2 ; C912.2 v1(16.35,20.67) ; 5.14,48.73 v1(5.14,48.07) ; v1(18.32,45.75) C926.2 ; C946.2 5.8,19.26 v1(5.73,19.34) ; U902.3 v1(3.52,40.14) ; v1(71.05,44.03) 71.05,44.02 R612.2 ; R933.2 2.03,53.86 C913.2 v1(2.02,53.24) ; v1(2.3,10.48) C943.2 ; v1(37.77,23.7) 37.5,23.96 C935.2 ; 5.47,9.05 5.47,8.45 v1(5.72,8.2) ; R1024.2 2.34,14.32 C947.2 v1(2.35,13.76) ; v1(3,10.35) 3.28,10.07 C944.2 ; v1(5.26,59.22) C911.2 ; v1(16.75,46.27) 16.64,46.38 R981.2 ; R610.2 65.6,44.39 v1(64.9,44.39) 64.21,44.39 R609.2 ; C909.2 v1(15.27,21.09) ; C403.2 v1(66.93,49.81) ; v1(31.15,17.61) 30.92,17.38 C709.2 ; C953.2 v1(16.59,26.32) ; C713.2 28.33,13.95 v1(28.61,13.67) ; v1(16.04,52.87) R978.2 ; v1(26.17,20.2) 26.16,20.2 25.74,20.62 C706.1 ; v1(1.78,29.42) R993.2 ; C401.2 v1(64.44,54.65) ; C404.2 v1(66.9,46.2)
  TOP w0.381: v1(34.87,54.45) C915.2 33.79,54.56 33.79,55.13 33.63,55.28 C916.2 v1(34.97,56.45) ; v1(22.15,17.69) C729.2 ; v1(33.93,18.87) 33.43,19.36 C1013.1 ; v1(22.79,20.05) 23.3,20.05 C730.2 ; TP801.1 v1(14.18,57.57) ; v1(27.11,7.65) 27.11,8.18 R1088.2 ; R955.2 14.74,41.75 C925.2 14.74,40.14 v1(14.9,39.98) ; v1(21.93,14.36) 21.93,14.82 v1(21.98,14.87) C725.2 ; R416.2 57.69,56.34 v1(57.48,56.56) ; v1(45.75,13.98) C923.2 C922.2 ; C996.1 22.55,19.03 22.38,18.87 21.81,18.87 v1(21.72,18.78) ; C1022.2 28.35,21.69 28.02,22.02 27.62,22.02 C704.1 v1(27.49,22.69) ; R417.2 v1(63.14,56.4) 63.12,56.39 R418.2 ; v1(31.88,20.56) 31.76,20.68 C731.2 ; v1(26.14,13.98) C1021.2 ; U907.3 v1(16.64,39.99) ; v1(21.95,15.35) 21.95,15.54 C724.1 ; TP804.1 69.95,9.26 v1(71.29,9.26) ; v1(25.6,55.66) C928.2 ; v1(19.84,46.78) R982.2 ; v1(24.36,55.71) C929.2 ; Y401.4 v1(65.72,49.95) ; C942.2 v1(37.67,52.19)
  BOTTOM w0.152: C109.2 52.55,38.95 52.55,38.76 v1(52.72,38.6)
  BOTTOM w0.203: v1(28.81,22.77) 28.81,22.45 R1100.2 ; J803.10 v1(70.18,41.84) ; v1(52.48,54.2) 53.08,54.8 J802.49 ; J802.14 v1(45.88,59.29) ; J801.46 v1(57.2,7.65) ; J802.8 v1(44.68,59.29) ; v1(54.47,56.57) 54.28,56.38 J802.55 ; v1(59.25,56.61) 59.08,56.43 J802.79 ; J801.35 v1(59.2,11.73) ; J802.76 58.28,59.18 v1(58.4,59.3) ; J802.13 v1(45.88,55.26) ; C139.2 49.64,37.07 v1(49.73,37.15) 49.73,37.23 49.46,37.5 C136.2 49.46,37.9 v1(49.76,38.2) 49.76,38.44 49.6,38.59 C154.2 49.6,39.04 v1(49.76,39.2) 49.46,39.5 C151.2 49.46,39.89 v1(49.76,40.2) ; v1(56.26,59.3) 56.28,59.28 J802.66 ; J801.65 v1(53.2,11.69) ; v1(51.72,37.2) 51.92,37.2 C146.2 ; v1(51.99,11.64) 52,11.63 J801.71 ; v1(34.97,56.45) 34.97,56.46 J901.2 ; v1(60.29,9.29) 60.8,8.78 J801.28 ; J803.39 v1(66.15,35.84) ; J803.76 v1(70.18,28.64) ; J802.31 v1(49.48,55.26) ; v1(51.28,38.18) 51.23,38.23 C140.2 51.23,39.08 v1(51.28,39.13) ; J802.38 50.68,59.44 v1(50.61,59.51) ; J801.45 v1(57.2,11.7) ; J802.2 v1(43.48,59.29) ; J803.50 v1(70.18,33.84) ; v1(50.77,42.72) 51.17,42.32 C147.2 ; J802.7 v1(44.68,55.26) ; J802.1 v1(43.48,55.26) ; J802.32 v1(49.48,59.29) ; J801.72 v1(52,7.67) ; J803.40 v1(70.22,35.84) ; J803.57 66.17,32.24 65.8,31.88 v1(65.77,31.88) ; J802.43 v1(51.88,55.26) ; J802.44 51.88,58.1 v1(51.76,57.98) ; J802.48 52.68,59.18 52.77,59.27 v1(52.77,59.32) ; v1(55.17,11.8) 55.2,11.77 J801.55 ; J803.9 v1(66.15,41.84) ; J803.30 v1(70.18,37.84) ; J901.12 34.86,54.46 v1(34.87,54.45) ; J803.29 v1(66.15,37.84) ; J802.20 v1(47.08,59.29) ; J803.68 v1(70.18,30.24) ; v1(60.79,7.55) 60.4,7.94 J801.30 ; J801.52 v1(56,8.99) ; J803.20 v1(70.18,39.84) ; v1(35.28,23.96) 35.28,23.93 34.68,23.33 34.39,23.33 v2(34.32,23.4) ; v1(56.95,59.32) 57.08,59.19 J802.70 ; v1(56.45,56.8) 56.28,56.63 J802.65 ; J802.71 v1(57.48,56.56) ; J802.60 55.08,59.34 v1(55.14,59.4) ; J803.49 v1(66.15,33.84) ; v1(52.72,38.6) 52.72,38.6 52.72,38.68 53.01,38.97 C106.2 53.11,39.22 53.11,39.61 C111.2 53.26,39.77 C101.2 53.28,40.17 v1(53.72,40.17) ; J803.75 v1(66.15,28.64) ; J802.37 v1(50.68,55.26) ; J803.67 v1(66.15,30.24) ; v1(67.57,39.84) J803.19 ; J801.62 v1(54,8.98) ; J803.60 v1(70.22,31.84) ; J802.19 v1(47.08,55.26) ; J801.36 v1(59.2,8.97) ; J802.25 v1(48.28,55.26) ; J802.54 v1(53.88,59.36) ; J802.26 v1(48.28,59.29)
  BOTTOM w0.254: v1(51.28,38.18) 51.28,37.77 C138.2 ; v1(56.78,41.13) 56.78,40.87 56.57,40.66 C148.2 ; C506.2 54.12,19.91 v1(54.1,19.93) ; C116.2 51.29,34.26 51.66,34.63 v1(51.75,34.63) ; C217.2 41,38.28 v1(40.97,38.3) ; C208.2 38.1,36.5 v1(37.92,36.68) ; C213.2 31.99,35.9 v1(31.93,35.85) ; C501.2 57.58,19.07 v1(57.58,18.43) ; C135.2 56.51,38.74 56.72,38.95 v1(56.72,39.2) ; C211.2 36.63,40.77 v1(36.47,40.62) ; v1(28.03,40.65) 28.09,40.7 C219.2 ; C206.2 36.52,32.64 v1(36.48,32.68) ; v1(29.33,32.65) 29.42,32.56 C222.2 ; v1(49.76,40.2) 49.66,40.29 C152.2 ; C138.2 51.85,37.74 C108.2 51.88,37.36 v1(51.72,37.2) 51.27,37.2 C137.2 ; C138.2 51.32,37.43 51.24,37.35 C137.2 ; v1(37.92,38.22) 37.95,38.19 C214.2 ; v1(53.72,37.2) 53.7,37.17 C117.2 ; v1(53.72,37.2) 54.12,37.2 C131.2 54.55,37.13 v1(54.67,37.25) ; v1(53.72,37.2) 53.7,37.22 C107.2 ; C509.2 59.74,23.89 C508.2 v1(59.19,23.9) ; v1(33.88,34.25) 33.87,34.23 R201.2 ; v1(61.54,19.84) 61.05,19.84 C504.2 ; C129.2 55.85,34.67 v1(55.83,34.69) ; C102.2 53.76,40.22 v1(53.72,40.17) ; C102.2 54.23,40.2 C110.2 54.23,39.32 54.18,39.27 54.18,39.22 v1(54.16,39.19) 54.26,39.09 54.26,38.29 v1(54.17,38.2) 54.26,38.11 C145.2 54.2,37.69 C107.2 ; C102.2 54.6,40.22 v1(54.69,40.13) ; C207.2 33.14,42.34 v1(33.23,42.25) ; C212.2 33.31,32.57 v1(33.23,32.65) ; C144.2 50.12,42.38 49.75,42.75 v1(49.66,42.75) ; C505.2 54.15,20.97 v1(54.13,20.99) ; C205.2 38.36,39.84 v1(38.42,39.9) 38.44,39.93 C221.2 ; C114.2 53.7,37.69 C107.2 ; C502.2 57.99,20.05 v1(57.97,20.03) ; C137.2 50.84,37.22 v1(50.81,37.26) ; C216.2 40.51,42.08 v1(40.39,42.2) ; v1(31.93,34.25) 31.99,34.3 C209.2 ; v1(56.72,42.7) 56.38,42.7 56.21,42.52 C149.2 ; C130.2 56.55,39.69 56.79,39.93 v1(56.79,40.23) ; C220.2 29.4,35.92 v1(29.33,35.85) ; v1(42.68,34.62) 42.6,34.7 C218.2 ; R208.1 35.73,39.02 v1(35.81,39.1) 35.72,39.19 R207.1 ; C210.2 32.01,38.97 v1(31.93,39.05) ; v1(36.48,35.09) 36.76,35.37 C203.2 ; v1(47.41,44.01) 47.98,43.44 R204.2 ; C507.2 56.61,21.44 56.61,21.27 v1(56.87,21.01) ; v1(54.75,42.71) 54.63,42.83 R303.2 ; C119.2 56.91,38.41 v1(56.72,38.22) ; v1(55.71,42.71) 55.36,42.71 R305.2 ; C118.2 56.76,37.23 v1(56.72,37.2) ; C204.2 v1(39.5,42.38) ; v1(49.73,34.67) 49.79,34.67 50.2,35.08 C141.2 ; v1(31.93,42.25) 32.01,42.32 C201.2 ; v1(48.69,36.19) 48.69,35.71 C156.2 ; C155.2 52.15,43.08 52.25,42.98 R302.1 51.73,42.73 v1(51.7,42.77) ; C134.2 51.98,40.21 v1(51.67,40.21) 51.43,40.45 C132.2 50.91,40.2 v1(50.77,40.2) 51.22,39.75 C124.2 51.28,39.6 v1(51.28,39.13) ; v1(56.01,19.03) 56.01,19.03 C503.2 ; v1(29.33,42.25) 29.18,42.4 C215.2
  BOTTOM w0.305: v1(37.81,32.72) 37.68,32.59 C202.2 ; v1(53.62,53.7) 53.82,53.9 C809.2 ; C952.2 v1(41.51,16.73)
  BOTTOM w0.381: v1(31.58,13.55) 31.58,14.45 C712.1 30.69,14.6 30.69,14.15 30.33,13.8 v1(30.33,13.6) ; C405.2 53.7,52.84 v1(53.64,52.78) ; v1(34.31,18.35) 34.31,17.13 C702.1 33.76,17.26 v1(33.76,18.32) ; R1099.2 v1(34.6,12.86)
  vias: v1(0.73,41.6) v1(0.74,39.63) v1(0.73,34.15) v1(0.7,20.33) v1(0.74,17.5) v1(0.74,15.55) v1(0.71,12.77) v1(0.72,7.96) v1(0.74,6.71) v1(0.71,5.44) v1(0.74,4.38) v1(0.74,3.22) v1(0.82,59.47) v1(0.77,58.55) v1(0.77,57.28) v1(0.79,55.9) v1(0.77,54.77) v1(0.78,53.73) v1(0.82,52.66) v1(0.78,51.56) v1(0.84,45.24) v1(0.75,44.24) v1(0.82,42.83) v1(0.83,37.06) v1(0.82,35.69) v1(0.82,32.67) v1(0.82,30.47) v1(0.79,28.9) v1(0.77,26.5) v1(0.87,46.24) v1(0.89,38.18) v1(0.9,21.98) v1(1.01,1.01) v1(1.14,60.16) v1(1.11,23.59) v1(1.25,50.93) v1(1.29,25.07) v1(1.43,47.17) v1(1.53,48.11) v1(1.56,50.05) v1(1.56,49.11) v1(1.94,6.83) v1(1.92,5.81) v1(2.02,33.25) v1(2.05,0.99) v1(2.13,60.26) v1(2.76,18.8) v1(2.9,60.31) v1(2.94,0.97) v1(2.97,21.98) v1(3.05,31.21) v1(3.25,35.91) v1(3.27,38.03) v1(3.31,33.99) v1(3.32,24.47) v1(3.64,11.98) v1(3.92,60.31) v1(4.24,1.53) v1(4.34,7.25) v1(4.34,6.12) v1(4.37,4.89) v1(5.23,0.83) v1(5.26,60.31) v1(6.46,60.31) v1(8.26,59.62) v1(8.57,10.45) v1(8.6,9.62) v1(8.97,11.16) v1(8.97,10.07) v1(9.51,59.54) v1(10.62,59.62) v1(11.31,59.9) v1(11.31,19.13) v1(12.07,60.38) v1(13.25,60.36) v1(15.36,60.39) v1(16.8,60.4) v1(18.59,60.4) v1(20.37,60.36) v1(21.19,12.25) v1(22,12.96) v1(22.14,60.36) v1(22.61,13.39) v1(23.92,60.36) v1(25,6.71) v1(25.53,6.56) v1(25.7,60.36) v1(26.07,6.61) v1(26.47,18.57) v1(26.57,17.48) v1(26.6,16.39) v1(26.65,6.61) v1(27.48,60.36) v1(27.56,18.52) v1(27.59,17.48) v1(27.56,16.42) v1(28.63,18.52) v1(28.63,17.48) v1(28.66,16.42) v1(29.26,60.36) v1(31.03,60.36) v1(31.83,12.78) v1(31.81,12.28) v1(32.37,12.55) v1(32.81,60.36) v1(34.59,60.36) v1(36.37,60.36) v1(36.94,11.84) v1(37.7,11.82) v1(38.15,60.36) v1(38.59,12.5) v1(38.99,31.83) v1(39.05,43.05) v1(39.92,60.36) v1(40.52,11.72) v1(41.7,60.36) v1(42.82,41.84) v1(42.85,33.08) v1(42.94,38.01) v1(43.48,53.59) v1(43.8,37.45) v1(44.12,60.36) v1(44.71,53.66) v1(45.3,60.4) v1(45.89,53.63) v1(46.48,60.34) v1(47.12,53.66) v1(47.74,60.31) v1(48.29,53.66) v1(48.72,42.72) v1(48.72,42.17) v1(48.69,41.15) v1(48.65,40.18) v1(48.69,39.2) v1(48.69,38.2) v1(48.69,37.2) v1(48.73,35.18) v1(48.73,34.65) v1(48.97,60.24) v1(49.51,53.66) v1(50.67,53.65) v1(51.72,60.35) v1(51.89,53.66) v1(56.83,60.33) v1(58.61,60.33) v1(60.39,60.33) v1(61.53,59.05) v1(61.5,57.95) v1(62.16,60.33) v1(62.46,5.9) v1(62.46,5.04) v1(62.99,10.37) v1(63.01,9.1) v1(63.31,59.05) v1(63.28,57.95) v1(63.6,60.32) v1(63.79,9.1) v1(63.86,10.38) v1(65.33,57.87) v1(65.41,59.06) v1(66.44,56.94) v1(67.03,22.6) v1(67.02,21.88) v1(67.54,58.94) v1(67.62,27.28) v1(67.6,26.64) v1(67.93,56.83) v1(68.1,58.05) v1(68.54,59.24) v1(68.79,55.07) v1(68.79,27.28) v1(68.82,26.54) v1(68.93,60.32) v1(69.06,21.85) v1(69.06,20.94) v1(69.34,13.79) v1(69.54,11.2) v1(69.71,21.84) v1(69.71,20.94) v1(69.69,7.36) v1(70.14,53.98) v1(70.32,52.73) v1(70.45,60.33) v1(71,54.44) v1(71.13,12.39) v1(71.25,0.84) v1(71.96,51.67) v1(72.09,52.73) v1(72.23,60.33) v1(72.68,16.9) v1(72.65,15.05) v1(72.88,13.77) v1(72.97,1.3) v2(6.95,2.06) v2(14.41,32.95) v3(5.04,53.53) v3(5.03,52.45) v3(5.06,54.57) v3(5.14,40.47) v3(5.12,39.39) v3(5.16,41.51) v3(5.74,27.51) v3(5.75,26.42) v3(5.75,14.05) v3(5.73,12.97) v3(5.76,28.55) v3(5.77,15.09) v3(6.12,54.53) v3(6.11,53.53) v3(6.09,52.46) v3(6.21,41.47) v3(6.21,40.47) v3(6.19,39.4) v3(6.46,28.53) v3(6.51,27.5) v3(6.49,26.43) v3(6.6,15.05) v3(6.6,14.05) v3(6.58,12.98) v3(7.13,53.49) v3(7.16,54.55) v3(7.16,52.46) v3(7.23,40.43) v3(7.22,28.55) v3(7.19,27.49) v3(7.22,26.46) v3(7.26,41.49) v3(7.26,39.4) v3(7.32,14.03) v3(7.35,15.09) v3(7.35,13) v3(18.24,39.24) v3(18.27,41.36) v3(18.25,40.32) v3(19.08,41.37) v3(19.08,40.31) v3(19.08,39.27) v3(20.42,41.36) v3(20.42,40.24) v3(20.42,39.23) v3(21.5,50.79) v3(21.58,51.68) v3(22.28,51.67) v3(22.3,50.78)
PVIN_LDO2: length 4.1
  TOP w0.203: 24.34,18.19 24.86,17.67 U701.20
  TOP w0.254: C996.2 23.85,19.03 24.09,18.8 24.09,18.45 24.34,18.19
  TOP w0.305: v1(23.48,18.44) 23.65,18.61 23.65,18.79 23.87,19.01
  BOTTOM w0.203: R1085.2 R1084.2
  BOTTOM w0.254: R1085.2 23.51,18.56 23.48,18.52 v1(23.48,18.44)
PVIN_LDO34: length 4.1
  TOP w0.254: U701.22 24.79,16.87 24.19,16.26 23.97,16.26 C724.2
  TOP w0.305: v1(23.67,16.57) C724.2
  BOTTOM w0.203: v1(23.67,16.57) 23.56,16.68 R1070.2 R1069.2
VBUS1_DET_3V3: length 21.5
  TOP w0.203: v1(53.75,41.2) 53.75,41.2 U101.F12
  TOP w0.254: R301.1 51.64,59.73 v1(51.73,59.82)
  L3_INT_1 w0.203: v1(53.75,41.2) 53.29,41.66 53.29,50.2 54.49,51.4 54.49,55.19 52.96,56.72 52.96,58.02 51.72,59.26 51.72,59.81 v1(51.73,59.82)
VBUS2_DET_3V3: length 20
  TOP w0.091: U101.E14 v1(54.75,41.7)
  L3_INT_1 w0.114: v1(54.75,41.7) 54.76,41.7 55.09,42.03 55.09,58.1 54.55,58.63 54.55,59.6 54.15,60 v1(54.08,60)
  BOTTOM w0.112: R304.1 54.54,59.96 54.5,60 v1(54.08,60)
VDD2_DDR: length 35.9
  TOP w0.203: v1(12.01,51.87) 11.57,51.87 R939.1 ; v1(12.12,52.99) 13.8,51.31 13.8,38.47 18.64,33.62 18.64,32.92 19.01,32.55 19.51,32.55 ; R958.1 19.61,34.65 19.61,33.6 20.08,33.14 22.3,33.14 23.2,32.24 23.2,28.79 22.93,28.52 22.1,28.52
  BOTTOM w0.203: v1(12.01,51.87) 12.06,51.92 12.06,52.93 v1(12.12,52.99)
  vias: v1(21.25,31.89) v1(21.19,29.75) v1(21.44,29.19) v1(21.8,31.89) v1(21.81,31.36) v1(22.16,29.19) v1(49.75,36.21) v1(50.24,37.19) v1(50.27,38.21) v1(50.7,36.71) v1(50.77,39.12) v1(50.77,38.16)
VDD_1P8: length 53
  BOTTOM w0.203: R1044.1 8.82,39.29 8.82,18.9 10.47,17.25 10.47,2.67 11.9,1.24 20.22,1.24 21.37,2.39 21.37,5.13 v1(21.67,5.43)
VDD_1V8: length 86.5
  TOP w0.112: v1(55.93,20.99) U501.M4
  TOP w0.203: U501.P5 54.15,20.49 v1(54.13,20.48) ; U501.N4 55,20.99 54.78,21.22 54.78,21.23 U501.P3 54.17,21.49 v1(54.1,21.56) ; R1028.1 11.94,13.13 12.34,12.73 12.97,12.73 13.55,12.15 13.55,10.26 14.58,9.24 14.58,8.19 R106.2 ; v1(12.83,14.69) 12.56,14.69 12.29,14.43 R1005.1
  TOP w0.254: v1(59.6,20.01) 60,20.01 U501.C6
  TOP w0.381: v1(57.29,26.67) 57.65,26.31 R501.1 ; R502.1 v1(54.97,26.7)
  BOTTOM w0.203: v1(12.83,14.69) 13.21,14.32 13.21,10.26 13.94,9.52 15.75,9.52 16.87,10.65 16.87,11.72 v1(17.25,12.1) ; v1(20.83,5.85) 20.96,5.72 20.96,2.6 19.94,1.57 12.03,1.57 10.85,2.76 10.85,17.33 9.15,19.04 9.15,39.1 R1045.1 ; R713.1 38.56,10.34 Q902.1
  BOTTOM w0.254: C506.1 54.16,20.45 v1(54.13,20.48) ; R713.1 39.1,13.14 39.76,13.8 42.14,13.8 Q903.1 42.61,13.33 43.14,13.33 43.14,13.34 R712.1 v1(43.77,13.9) ; C507.1 56.08,21.44 56.08,21.14 v1(55.93,20.99) ; v1(59.6,20.01) C504.1 ; C505.1 54.16,21.51 v1(54.1,21.56)
  vias: v1(19.34,12.07) v1(19.31,11.49) v1(19.34,10.88) v1(61.3,10.35) v1(61.3,9.72) v1(61.27,9.08) v1(61.95,9.08) v1(61.97,10.32) v1(61.98,9.72)
VDD_3P3: length 62.4
  TOP w0.203: R726.1 29.65,4.07 28.96,3.39 TP957.1 28.96,1.38 28.58,1 12.12,1 10.95,2.17 v1(9.45,2.17)
  TOP w0.381: C715.2 33.39,10.63 33.99,11.23 33.99,13.47 v1(34.37,13.85)
  BOTTOM w0.203: v1(9.45,2.17) 9.4,2.22 9.4,15.63 8.44,16.59 8.44,34.15 R1042.1
  BOTTOM w0.381: R1092.2 v1(34.37,13.85)
VDD_3V3: length 216.3
  TOP w0.203: U501.F5 v1(58.51,20.03) 58.55,19.99 U501.E6 ; R991.1 8.67,21.7 v1(9.71,21.7) ; 32.25,1.16 32.25,1.13 31.72,0.61 11.8,0.61 10.72,1.68 9.3,1.68 8.9,2.09 v1(8.9,2.93) ; v1(56.04,18.49) U501.K9 ; v1(7.19,33.18) 7.65,33.18 7.88,32.95 7.88,32.75 R987.1 ; v1(57.01,18.46) U501.J10
  TOP w0.254: v1(68.16,19.84) 68.16,20.18 TP958.1
  TOP w0.381: R605.1 67.93,19.61 v1(68.16,19.84)
  L3_INT_1 w0.203: v1(40.11,2.31) 39.83,2.59 39.54,2.59 38.23,1.27 14.29,1.27 10.32,5.24 8.29,5.24 6.25,7.27 6.25,9.8 7.98,11.53 7.98,15.8 6.31,17.47 6.31,24.67 8.08,26.45 8.08,30.87 6.89,32.06 6.89,32.87 v1(7.19,33.18) ; v1(36,2.55) 35.56,2.55 31.75,6.36 27.82,6.36 27.57,6.1 24.36,6.1 23.04,7.42 14.87,7.42 10.37,11.92 10.37,17.3 9.06,18.62 9.06,20.87 9.71,21.52 v1(9.71,21.7)
  L3_INT_1 w0.381: v1(21.21,19.21) 21.21,20.25 23.12,22.16 29.67,22.16 30.75,21.08 32.1,21.08 32.44,20.74 v1(32.44,20.68)
  BOTTOM w0.203: v1(8.9,2.93) 8.9,8.52 8.01,9.41 8.01,33.52 R1043.1
  BOTTOM w0.254: v1(57.01,18.46) 56.92,18.55 56.92,19.06 C501.1 ; C503.1 56.04,18.5 v1(56.04,18.49) ; C502.1 58.53,20.05 v1(58.51,20.03)
  BOTTOM w0.381: R1065.1 32.44,20.12 v1(32.44,20.68) ; v1(21.21,19.21) 21.44,19.44 22.03,19.44 22.26,19.21 R1084.1
  BOTTOM w0.457: R1084.1 22.77,18.21 22.82,18.16 R1069.1 22.82,17.21 22.18,16.57
  BOTTOM w0.686: 32.39,2.75 31.88,2.75 30.05,4.58 30.05,6.38 28.73,7.7 28.02,7.7 27.29,8.44 21.44,8.44 20.01,9.87 20.01,13.02 21.16,14.18 21.16,15.55 22.18,16.57
  vias: v1(34.27,2.34) v1(36.52,2.55) v1(37.04,2.55) v1(40.65,2.33) v1(68.18,24.62) v1(68.15,23.93) v1(68.68,24.62) v1(68.66,23.93) v1(70.18,24.49) v1(70.18,23.88)
VDD_ANA_0P8: length 15.8
  TOP w0.203: v1(53.72,36.69) 53.73,36.7 U101.R14 ; R1000.1 12.39,25.98 15.68,22.69 18.79,22.69 19.2,22.28 19.2,21.79 18.7,21.29 18.7,20.97 ; U101.F10 v1(52.71,41.2) ; U101.G8 51.75,40.7 v1(51.76,40.71) ; U101.J15 54.72,39.29 54.67,39.24 v1(54.67,39.21)
  TOP w0.254: v1(55.19,39.2) 55.22,39.24 U101.J16
  BOTTOM w0.152: v1(51.76,40.71) 51.75,40.71 51.59,40.71 51.42,40.88 51.27,40.88 C132.1
  BOTTOM w0.203: C131.1 54.1,36.69 v1(53.72,36.69) ; v1(52.71,41.2) 52.43,41.2 C134.1
  BOTTOM w0.254: C135.1 54.67,38.9 v1(54.67,39.21) ; v1(55.19,39.2) 55.19,39.66 C130.1
  vias: v1(17.38,21.88) v1(17.35,21.37) v1(17.91,21.85) v1(17.91,21.22)
VDD_ANA_0V8: length 16
  TOP w0.203: R997.1 15.77,23.07 18.92,23.07 19.72,22.27 19.72,21.25 20,20.97
  TOP w0.254: C730.1 24.16,19.95 24.48,19.63 24.48,18.63 25.04,18.07 U701.19
  TOP w0.508: 20,20.97 20,19.45 20.03,19.42
VDD_ANA_1P8: length 70.3
  TOP w0.203: U101.F6 50.7,41.2 v1(50.72,41.21) ; v1(51.72,36.69) 51.72,36.7 U101.R8 ; U101.F16 55.67,41.2 v1(55.72,41.15) ; v1(51.78,41.22) 51.76,41.2 U101.F8 U101.E8 ; R909.1 7.25,19.18 7.25,19.94 6.8,20.38 2.63,20.38 1.81,19.56 1.81,12.66 3.99,10.48 4.04,10.43 4.04,8.88 7.23,5.69 8.1,5.69 8.56,6.15 9.41,6.15 9.47,6.09
  TOP w0.254: U101.G16 55.22,40.21 v1(55.21,40.19) ; v1(54.69,38.24) 54.72,38.27 U101.L15
  L3_INT_1 w0.305: v1(54.69,38.24) 54.69,38.35 55,38.65 63.64,38.65 v1(63.9,38.38)
  L3_INT_1 w0.381: v1(48.34,12.89) 48.34,22.61 46.3,24.66 v1(46.28,24.66)
  BOTTOM w0.152: C149.1 56.2,41.63 v1(55.72,41.15)
  BOTTOM w0.203: C147.1 51.23,41.57 51.57,41.22 v1(51.78,41.22) ; C144.1 50.47,41.21 v1(50.72,41.21) ; C146.1 52.07,36.38 51.75,36.69 v1(51.72,36.69)
  BOTTOM w0.254: C145.1 54.79,38.14 v1(54.69,38.24) ; v1(55.21,40.19) 55.21,40.38 C148.1
  BOTTOM w0.305: C146.1 52.21,33.17 49.45,30.4
  BOTTOM w0.381: v1(46.28,24.66) 45.57,25.36 45.57,26.53 49.45,30.4
  vias: v1(11.33,7.78) v1(11.41,6.87) v1(11.84,7.8) v1(11.94,6.89)
VDD_ANA_1V8: length 29
  TOP w0.203: R905.1 7.58,19.21 7.58,20.09 6.95,20.71 2.49,20.71 1.45,19.68 1.45,12.55 3.71,10.29 3.71,8.74 7.09,5.35 8.23,5.35 9.15,4.43 R1001.1 ; TP938.1 9.01,4.25
VDD_SNVS_0V8: length 1.1
  TOP w0.203: v1(54.75,40.65) 54.72,40.68 54.66,40.68 54.64,40.7 U101.G14
  BOTTOM w0.254: C102.1 54.32,40.68 54.72,40.68 v1(54.75,40.65)
VDD_SOC: length 122
  TOP w0.203: U101.N11 v1(52.72,37.2) ; v1(6.85,46.49) 6.49,46.13 R1020.1 ; R927.1 6.63,58.83 v1(6.63,59.41)
  TOP w0.254: U101.J11 v1(52.72,40.13)
  BOTTOM w0.203: v1(6.63,59.41) 6.74,59.3 6.74,58.44 7.34,57.83 7.34,55.2 14.13,48.41 14.13,36.06 15.52,34.67 15.52,32.17 20.79,26.91 39.45,26.91 42.1,24.25 42.1,23.64 v1(41.61,23.15) ; v1(40.26,20.15) 40.26,19.74 40.75,19.26 41.48,19.26 41.84,19.62 41.84,21.7 40.11,23.43 38.68,23.43 35.89,26.22 20.49,26.22 15.27,31.43 13.72,31.43 12.84,32.31 12.84,35.56 13.29,36.01 13.29,42.93 11.51,44.71 7.67,44.71 6.85,45.53 v1(6.85,46.49)
  vias: v1(39.2,22.49) v1(39.22,21.88) v1(39.83,22.49) v1(39.86,21.9) v1(40.4,21.88) v1(40.47,22.49) v1(51.7,38.58) v1(52.21,38.58) v1(53.24,38.66) v1(53.76,38.69)
VDD_SOC_0V85: length 65
  TOP w0.203: 40.44,15.65 40.32,15.77 38.47,15.77 38.31,15.93 v1(38.06,15.93) ; R1008.1 7.6,46.23 v1(7.42,46.42)
  BOTTOM w0.203: v1(7.42,46.42) 7.18,46.19 7.18,45.66 7.81,45.04 11.65,45.04 13.62,43.07 13.62,35.87 13.17,35.42 13.17,32.44 13.85,31.76 15.41,31.76 20.62,26.55 36.03,26.55 38.79,23.78 40.29,23.78 42.25,21.83 42.25,19.49 41.69,18.93 41,18.93 40.75,18.68 v1(40.75,18.42) ; v1(38.06,15.93) 37.93,15.93 36.89,14.89 R1091.2
  vias: v1(36.56,17.03) v1(39.83,16.68) v1(40.75,16.69) v1(41.8,15.78) v1(43.29,18.6) v1(43.31,17.91) v1(44.43,18.6) v1(44.46,17.91) v1(45.55,18.57) v1(45.52,17.91)
VDD_USB_3P3: length 161.7
  TOP w0.203: U101.G10 52.71,40.7 v1(52.74,40.67) ; R996.1 8.18,21.11 v1(10.19,21.11)
  TOP w0.381: 35.17,3.55 35.03,3.55 34.84,3.36 33.86,3.36 33.65,3.14 R105.2
  L3_INT_1 w0.203: v1(36.07,3.16) 36.02,3.16 36,3.13 35.44,3.13 31.83,6.74 27.23,6.74 26.8,7.17 24.82,7.17 24.8,7.2 24.24,7.75 15.04,7.75 10.72,12.07 10.72,17.43 9.45,18.7 9.45,20.78 9.78,21.11 v1(10.19,21.11)
  L3_INT_1 w0.508: v1(35.79,4.5) 35.79,6.26 33.48,8.57 28.43,8.57 28.05,8.95 18.65,8.95 17.96,9.63 17.96,13.24 14.38,16.82 14.38,17.61 13.7,18.3 13.7,26.12 15.58,28 15.58,33.79 13.9,35.47 13.9,53.55 14.41,54.06 18.17,54.06 18.78,53.45 v3(18.78,52.85)
  BOTTOM w0.152: C155.1 52.69,42.98 53.09,42.57 53.09,41.08 52.74,40.72 v1(52.74,40.67)
  BOTTOM w0.305: 52.69,43.87 52.69,43.87 C155.1
  BOTTOM w0.508: 52.69,43.87 52.69,44.27 48.57,48.39 36.83,48.39 36.4,47.96 23.38,47.96 18.78,52.56 v3(18.78,52.85)
VDDQ_DDR: length 53.1
  TOP w0.203: R943.1 24.92,41.77 26.91,39.78 26.91,33.33 28.28,31.97 31.01,31.97 31.88,31.09 31.88,29.22 v1(32.15,28.95) ; U101.L6 50.27,38.74 v1(50.27,39.16) 50.22,39.2 U101.J6 ; U101.J6 50.27,39.74 v1(50.27,40.22) 50.22,40.27 U101.G6 50.72,40.7 v1(50.73,40.7) ; U101.J6 U101.J7 ; R947.1 19.41,45.74 v1(19.54,45.87)
  BOTTOM w0.203: v1(33.72,28.94) 34.27,29.5 34.27,30.72 33.96,31.03 23.27,31.03 19.57,34.74 19.57,45.85 v1(19.54,45.87)
  BOTTOM w0.254: C154.1 50.27,38.86 v1(50.27,39.16) 50.27,39.63 C151.1 ; v1(50.73,40.7) 50.72,40.69 C152.1 50.2,40.29 v1(50.27,40.22)
  vias: v1(32.65,28.98) v1(33.16,28.97)
